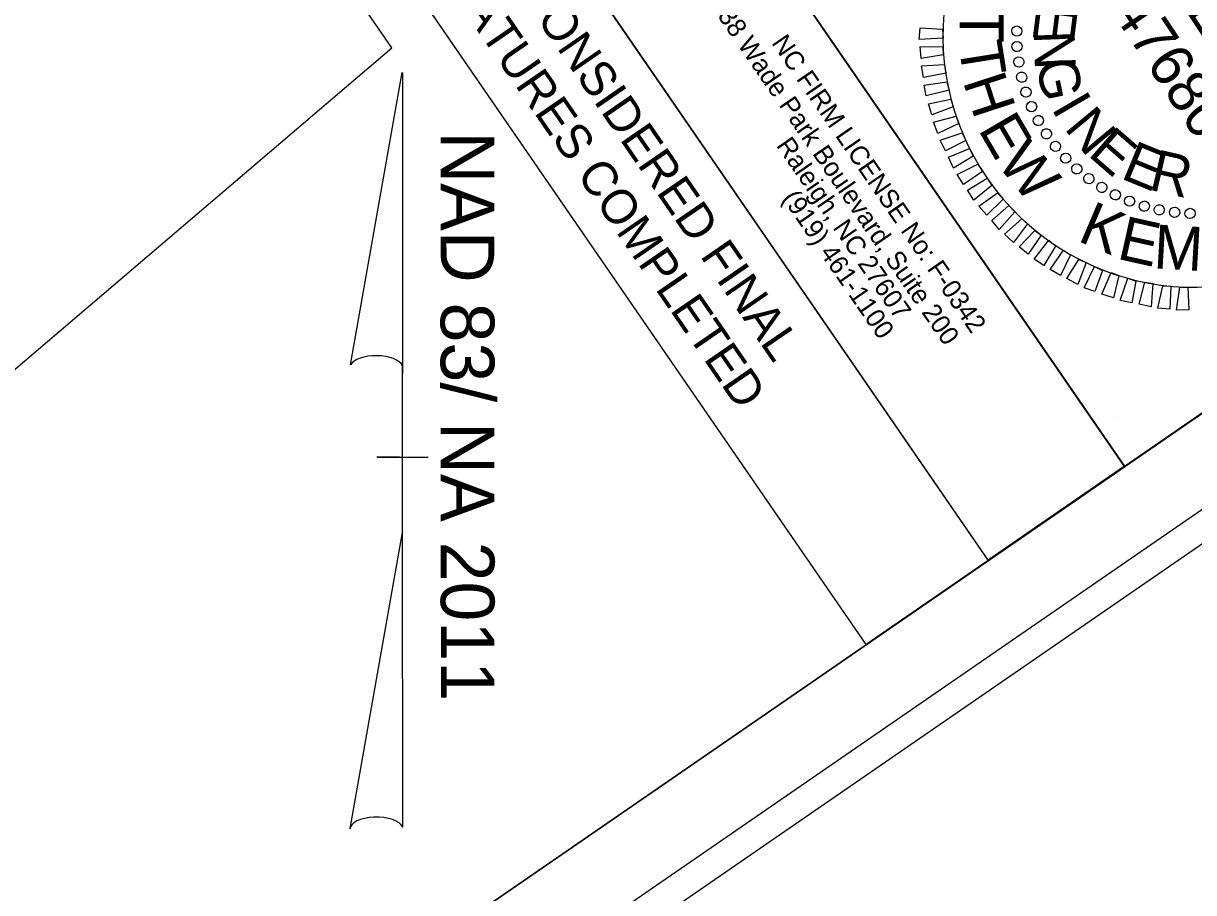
# Model space of a CAD drawing. Extents: x 2297526 to 2298642, y 599613 to 600819.
# Drawn here: x 2298445.3 to 2298556.7, y 599895.5 to 599978.2 of the extents above; entities that cross this region are included whole.
import ezdxf

# ---------------------------------------------------------------- set-up
doc = ezdxf.new("R2010")
doc.units = 0
for name, color, linetype in [('Exist DTM Drainline Cogo Comment', 7, 'Continuous'), ('Exist DTM Drainline Cogo Elevation', 7, 'Continuous'), ('Exist DTM Drainline Cogo Point CELL', 7, 'Continuous'), ('Exist Property Iron Pin CELL', 7, 'Continuous'), ('Exist Property Iron Pin Cogo Number', 7, 'Continuous'), ('Exist Roads Curbs Cogo Comment', 7, 'Continuous'), ('Exist Roads Curbs Cogo Number', 7, 'Continuous'), ('Exist Roads Curbs Cogo Point CELL', 7, 'Continuous'), ('Exist Roads EOP Cogo Elevation', 7, 'Continuous'), ('Exist Roads EOP Other Cogo Point CELL', 7, 'Continuous'), ('Exist Roads Soil Cogo Number', 7, 'Continuous')]:
    doc.layers.add(name, color=color, linetype=linetype)

msp = doc.modelspace()

# ---------------------------------------------------------------- linework, layer by layer
at = {"layer": 'Exist DTM Drainline Cogo Comment'}
msp.add_lwpolyline([(2298629.8, 599981.76), (2298062.67, 600805.27), (2297541.29, 600446.21), (2298108.42, 599622.7)], close=True, dxfattribs=at)
at = {"layer": 'Exist DTM Drainline Cogo Elevation'}
for points in [[(2298624.28, 599987.07), (2298113.82, 600728.3), (2297594.96, 600370.97), (2298105.42, 599629.74)], [(2298571.7, 600023.7), (2298605.73, 599974.29), (2298550.14, 599936), (2298516.11, 599985.42)]]:
    msp.add_lwpolyline(points, close=True, dxfattribs=at)
at = {"layer": 'Exist DTM Drainline Cogo Point CELL'}
msp.add_arc((2298556.8, 599977.02), 23.96, 124.5541, 304.5541, dxfattribs=at)
at = {"layer": 'Exist Property Iron Pin CELL'}
for p, q in [((2298476.45, 599945.68), (2298481.37, 599973.49)), ((2298481.4, 599973.49), (2298481.4, 599944.81)), ((2298481.4, 599929.93), (2298481.4, 599945.65)), ((2298481.4, 599944.81), (2298481.4, 599945.62)), ((2298479, 599936.89), (2298478.97, 599936.89)), ((2298481.13, 599936.89), (2298479, 599936.89)), ((2298479.03, 599936.89), (2298483.83, 599936.89)), ((2298481.4, 599929.93), (2298476.39, 599901.58)), ((2298481.43, 599901.7), (2298481.4, 599929.93))]:
    msp.add_line(p, q, dxfattribs=at)
for centre, start_param, end_param in [((2298478.93, 599945.38), 0.216388, 2.908219), ((2298478.93, 599901.48), 0.201328, 3.141593)]:
    msp.add_ellipse(centre, major_axis=(2.54, -0.02), ratio=0.461098, start_param=start_param, end_param=end_param, dxfattribs=at)
at = {"layer": 'Exist Property Iron Pin Cogo Number'}
msp.add_lwpolyline([(2297647.43, 600347.7), (2298036.32, 599783), (2298066.14, 599803.53), (2298144.6, 599689.59), (2298480.39, 599975.84), (2298444.85, 600027.45), (2298522.99, 600081.26), (2298287.23, 600423.6), (2298114.33, 600674.66)], close=True, dxfattribs=at)
at = {"layer": 'Exist Roads Curbs Cogo Comment'}
for p, q in [((2298469.09, 600025.93), (2298537.16, 599927.08)), ((2298525.55, 599919.08), (2298457.47, 600017.93)), ((2298537.16, 599927.07), (2298525.54, 599919.07))]:
    msp.add_line(p, q, dxfattribs=at)
at = {"layer": 'Exist Roads Curbs Cogo Number'}
msp.add_lwpolyline([(2298113.82, 600728.3), (2297594.98, 600370.97), (2298105.44, 599629.74), (2298525.54, 599919.07), (2298457.47, 600017.93), (2298556.21, 600085.92)], close=True, dxfattribs=at)
at = {"layer": 'Exist Roads Curbs Cogo Point CELL'}
msp.add_lwpolyline([(2298642.42, 599987.17), (2298069.34, 600819.33), (2297525.77, 600444.99), (2298098.85, 599612.83)], close=True, dxfattribs=at)
at = {"layer": 'Exist Roads EOP Other Cogo Point CELL'}
msp.add_lwpolyline([(2298482.06, 600034.86), (2298550.12, 599936.03), (2298537.15, 599927.1), (2298469.09, 600025.93)], close=True, dxfattribs=at)
at = {"layer": 'Exist Roads Soil Cogo Number'}
for p, q in [((2298539.87, 599977.45), (2298539.87, 599977.45)), ((2298539.86, 599975.97), (2298539.86, 599975.97)), ((2298540.05, 599974.5), (2298540.05, 599974.5)), ((2298540.32, 599973.04), (2298540.32, 599973.04)), ((2298540.73, 599971.61), (2298540.73, 599971.61)), ((2298541.29, 599970.27), (2298541.29, 599970.27)), ((2298541.91, 599968.94), (2298541.91, 599968.94)), ((2298542.67, 599967.66), (2298542.67, 599967.66)), ((2298543.54, 599966.45), (2298543.54, 599966.45)), ((2298544.53, 599965.37), (2298544.53, 599965.37)), ((2298545.6, 599964.3), (2298545.6, 599964.3)), ((2298546.74, 599963.37), (2298546.74, 599963.37)), ((2298547.95, 599962.56), (2298547.95, 599962.56)), ((2298549.25, 599961.86), (2298549.25, 599961.86)), ((2298550.62, 599961.24), (2298550.62, 599961.24)), ((2298551.98, 599960.75), (2298551.98, 599960.75)), ((2298553.45, 599960.41), (2298553.45, 599960.41)), ((2298554.88, 599960.17), (2298554.88, 599960.17)), ((2298556.37, 599960.09), (2298556.37, 599960.09)), ((2298549.32, 599940.64), (2298549.32, 599940.64))]:
    msp.add_line(p, q, dxfattribs=at)
for points in [[(2298532.88, 599976.77), (2298530.59, 599976.63), (2298530.68, 599977.76), (2298532.79, 599977.61)], [(2298532.87, 599975.17), (2298530.77, 599974.83), (2298530.67, 599975.99), (2298532.84, 599975.93)], [(2298533.11, 599973.45), (2298530.99, 599973.01), (2298530.79, 599974.14), (2298533, 599974.27)], [(2298533.45, 599971.83), (2298531.25, 599971.27), (2298531.05, 599972.28), (2298533.2, 599972.61)], [(2298533.81, 599970.24), (2298531.8, 599969.47), (2298531.48, 599970.52), (2298533.6, 599970.96)], [(2298534.36, 599968.66), (2298532.37, 599967.69), (2298531.94, 599968.79), (2298534.1, 599969.34)], [(2298535.03, 599967.03), (2298533.08, 599966.05), (2298532.59, 599967.07), (2298534.66, 599967.75)], [(2298535.73, 599965.54), (2298533.85, 599964.41), (2298533.38, 599965.44), (2298535.38, 599966.28)], [(2298536.6, 599964.09), (2298534.8, 599962.85), (2298534.19, 599963.79), (2298536.17, 599964.78)], [(2298537.5, 599962.74), (2298535.78, 599961.36), (2298535.18, 599962.29), (2298537.06, 599963.43)], [(2298538.59, 599961.45), (2298537.02, 599959.92), (2298536.26, 599960.78), (2298538.05, 599962.06)], [(2298539.68, 599960.23), (2298538.21, 599958.56), (2298537.49, 599959.42), (2298539.13, 599960.84)], [(2298540.9, 599959.1), (2298539.55, 599957.31), (2298538.71, 599958.12), (2298540.36, 599959.59)], [(2298542.18, 599958.02), (2298540.95, 599956.23), (2298540.11, 599956.92), (2298541.59, 599958.47)], [(2298543.57, 599956.96), (2298542.45, 599955.13), (2298541.54, 599955.73), (2298542.92, 599957.54)], [(2298544.99, 599956.14), (2298544.05, 599954.18), (2298543.06, 599954.77), (2298544.32, 599956.58)], [(2298546.48, 599955.41), (2298545.69, 599953.34), (2298544.65, 599953.9), (2298545.78, 599955.7)], [(2298548.02, 599954.66), (2298547.31, 599952.66), (2298546.28, 599953.01), (2298547.26, 599955.04)], [(2298549.58, 599954.18), (2298549.07, 599952.06), (2298547.97, 599952.41), (2298548.85, 599954.46)], [(2298551.21, 599953.66), (2298550.83, 599951.59), (2298549.7, 599951.8), (2298550.45, 599953.92)], [(2298552.81, 599953.41), (2298552.65, 599951.21), (2298551.53, 599951.47), (2298552.06, 599953.55)], [(2298554.54, 599953.17), (2298554.45, 599950.98), (2298553.31, 599951.09), (2298553.77, 599953.21)], [(2298556.17, 599953.06), (2298556.26, 599950.91), (2298555.09, 599950.88), (2298555.39, 599953.06)]]:
    msp.add_lwpolyline(points, close=True, dxfattribs=at)
for centre, major_axis in [((2298539.88, 599977.44), (-0.486, 0.012)), ((2298539.9, 599975.97), (-0.485, -0.03)), ((2298540.06, 599974.5), (-0.481, -0.072)), ((2298540.34, 599973.05), (-0.472, -0.114)), ((2298540.75, 599971.63), (-0.461, -0.155)), ((2298541.28, 599970.25), (-0.446, -0.194)), ((2298541.93, 599968.93), (-0.427, -0.232)), ((2298542.69, 599967.66), (-0.405, -0.269)), ((2298543.56, 599966.47), (-0.38, -0.303)), ((2298544.53, 599965.35), (-0.352, -0.335)), ((2298545.59, 599964.33), (-0.322, -0.364)), ((2298546.74, 599963.4), (-0.289, -0.391)), ((2298547.97, 599962.57), (-0.254, -0.415)), ((2298549.26, 599961.86), (-0.216, -0.435)), ((2298550.61, 599961.26), (-0.178, -0.452)), ((2298552.01, 599960.78), (-0.138, -0.466)), ((2298553.44, 599960.43), (-0.096, -0.476)), ((2298554.9, 599960.2), (-0.055, -0.483)), ((2298556.37, 599960.09), (-0.012, -0.486))]:
    msp.add_ellipse(centre, major_axis=major_axis, ratio=0.999708, dxfattribs=at)

# ---------------------------------------------------------------- texts
at = {"layer": 'Exist Property Iron Pin CELL'}
msp.add_text('NAD 83/ NA 2011', height=5.1, rotation=270.0239, dxfattribs=at).set_placement((2298485.03, 599967.9))
at = {"layer": 'Exist Roads Curbs Cogo Comment'}
for s, p in [('UNLESS ALL SIGNATURES COMPLETED', (2298465.07, 600011.5)), ('DOCUMENT NOT CONSIDERED FINAL', (2298471.15, 600011.99))]:
    msp.add_text(s, height=3.3, rotation=304.5541, dxfattribs=at).set_placement(p)
at = {"layer": 'Exist Roads EOP Cogo Elevation'}
for s, p in [('5438 Wade Park Boulevard, Suite 200', (2298509.81, 599981.11)), ('NC FIRM LICENSE No: F-0342', (2298516.47, 599976.31)), ('Raleigh, NC 27607', (2298516.92, 599966.56)), ('(919) 461-1100', (2298517.49, 599961.53))]:
    msp.add_text(s, height=1.8, rotation=304.5541, dxfattribs=at).set_placement(p)
at = {"layer": 'Exist Roads Soil Cogo Number'}
for s, height, rotation, p in [('SEAL', 4.049, 303.5541, (2298553.97, 599982.32)), ('047680', 4.05, 303.5541, (2298547.12, 599981.9)), ('T', 4.16, 270.0406, (2298534.45, 599979.7)), ('E', 3.93, 262.8309, (2298541.82, 599980.14)), ('N', 3.9, 272.188, (2298541.47, 599977.44)), ('T', 4.12, 279.0406, (2298534.31, 599976.17)), ('G', 3.86, 281.5443, (2298541.67, 599974.47)), ('H', 4.08, 288.0405, (2298534.72, 599972.66)), ('I', 3.81, 300.2553, (2298543.12, 599970.1)), ('E', 4.05, 300.282, (2298536.15, 599968.08)), ('N', 3.81, 309.6104, (2298544.32, 599968.18)), ('E', 3.83, 318.9658, (2298546.55, 599965.66)), ('W', 4.05, 309.5967, (2298537.87, 599964.85)), ('E', 3.9, 337.6781, (2298549.66, 599963.46)), ('R', 3.93, 347.0355, (2298552.33, 599962.38)), ('K', 4.15, 336.8961, (2298545.55, 599957.52)), ('E', 4.18, 347.4067, (2298549.3, 599955.8)), ('M', 4.18, 356.7213, (2298552.83, 599954.87))]:
    msp.add_text(s, height=height, rotation=rotation, dxfattribs=at).set_placement(p)

doc.saveas('drawing.dxf')
